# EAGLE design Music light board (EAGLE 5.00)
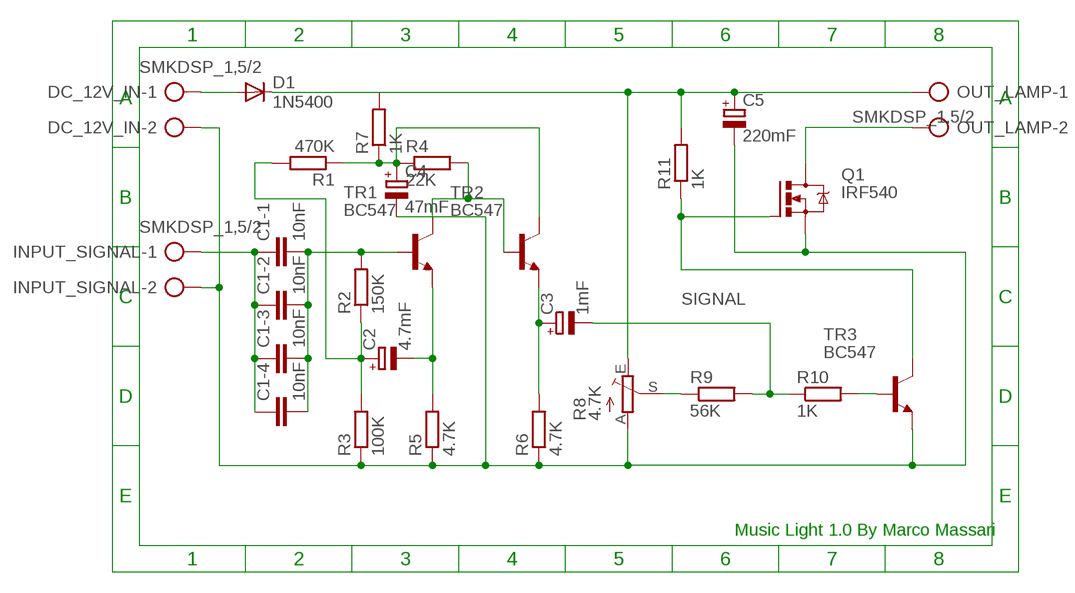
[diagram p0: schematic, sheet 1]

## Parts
C1-1  10nF  C-EU050-024X044  [C050-024X044]
C1-2  10nF  C-EU050-024X044  [C050-024X044]
C1-3  10nF  C-EU050-024X044  [C050-024X044]
C1-4  10nF  C-EU050-024X044  [C050-024X044]
C2  4.7mF  CPOL-EUE5-5  [E5-5]
C3  1mF  CPOL-EUE5-5  [E5-5]
C4  47mF  CPOL-EUE5-6  [E5-6]
C5  220mF  CPOL-EUE5-8.5  [E5-8,5]
D1  1N5400  [DO201-15]
DC_12V_IN  SMKDSP_1,5/2  [SMKDSP_1,5/2]
INPUT_SIGNAL  SMKDSP_1,5/2  [SMKDSP_1,5/2]
OUT_LAMP  SMKDSP_1,5/2  [SMKDSP_1,5/2]
Q1  IRF540  [TO220BV]
R1  470K  R-EU_0207/10  [0207/10]
R2  150K  R-EU_0207/10  [0207/10]
R3  100K  R-EU_0207/10  [0207/10]
R4  22K  R-EU_0207/10  [0207/10]
R5  4.7K  R-EU_0207/10  [0207/10]
R6  4.7K  R-EU_0207/10  [0207/10]
R7  1K  R-EU_0207/10  [0207/10]
R8  4.7K  TRIM_EU-LI10  [LI10]
R9  56K  R-EU_0207/10  [0207/10]
R10  1K  R-EU_0207/10  [0207/10]
R11  1K  R-EU_0207/10  [0207/10]
TR1  BC547  [TO92]
TR2  BC547  [TO92]
TR3  BC547  [TO92]

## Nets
N$1: D1.A DC_12V_IN.1
N$2: C1-1.1 C1-2.1 C1-3.1 C1-4.1 INPUT_SIGNAL.1
N$3: C1-1.2 C1-2.2 C1-3.2 C1-4.2 R2.2 TR1.2(B)
N$4: R8.S R9.1
N$5: R4.2 TR1.3(C) TR2.2(B)
N$6: C2.- R5.2 TR1.1(E)
N$7: C4.- C5.- DC_12V_IN.2 INPUT_SIGNAL.2 Q1.S R3.1 R5.1 R6.1 R8.A TR3.1(E)
N$8: C4.+ R1.1 R4.1 R7.1 TR2.3(C)
N$9: C5.+ D1.C OUT_LAMP.1 R7.2 R8.E R11.2
N$11: C3.+ R6.2 TR2.1(E)
N$13: Q1.G R11.1 TR3.3(C)
N$14: R10.2 TR3.2(B)
N$15: C2.+ R1.2 R2.1 R3.2
N$16: OUT_LAMP.2 Q1.D
SIGNAL: C3.- R9.2 R10.1

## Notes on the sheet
- Music Light 1.0 By Marco Massari

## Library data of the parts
C1-1-C1-4 = rcl:C-EU: CAPACITOR, European symbol
C2-C5 = rcl:CPOL-EU: POLARIZED CAPACITOR, European symbol
D1 = diode:1N5400: DIODE
DC_12V_IN INPUT_SIGNAL OUT_LAMP = con-phoenix-smkdsp:SMKDSP_1,5/2: Printklemme, Nennstrom: 17,5 A, Bemessungsspannung: 250 V, Raster: 5,0 mm
Q1 = transistor-power:IRF540: HEXFET Power MOSFET
R1-R7 = resistor:R-EU_: RESISTOR, European symbol
R8 = pot:TRIM_EU-: POTENTIOMETER
R9-R11 = rcl:R-EU_: RESISTOR, European symbol
TR1-TR3 = transistor-npn:BC547*: NPN Transistor

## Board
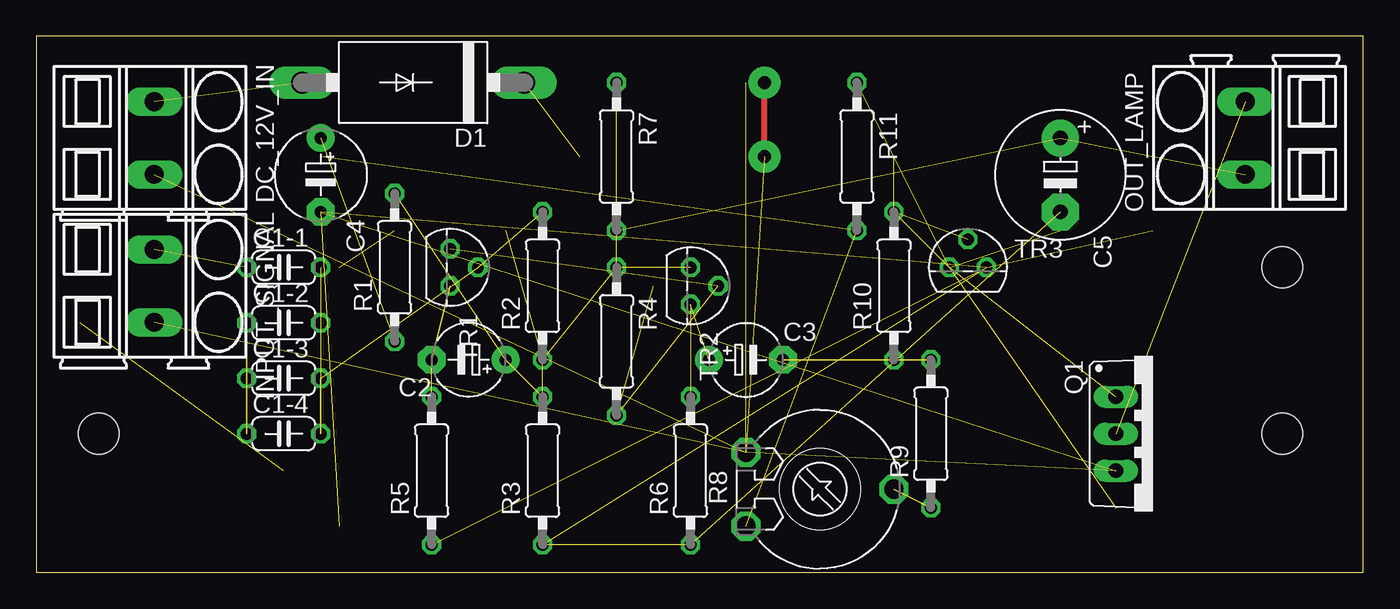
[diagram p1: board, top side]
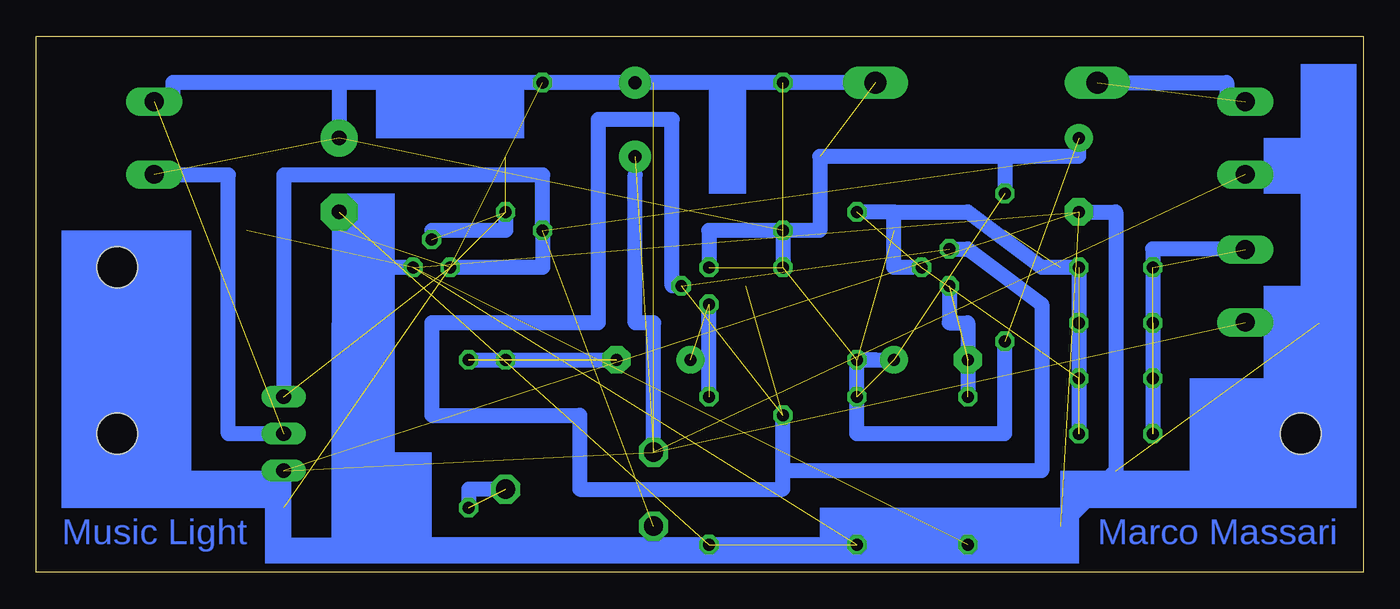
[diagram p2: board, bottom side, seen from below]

Size 91.11 x 36.82 mm. Coordinates in mm from the lower left corner, seen from the top.
Outline: 0,0 91.11,0 91.11,36.82 0,36.82 0,0
Copper layers (1*16): Top 0.035mm / dielectric 1.5mm / Bottom 0.035mm
Design rules "default": minimum track width 10mil, minimum drill 24mil, track to track 8mil, track to pad 8mil, pad to pad 8mil, via to via 8mil, smd to smd 8mil, copper to edge 40mil, drill to drill 8mil, minimum pad ring 10mil, minimum via ring 8mil, stop-mask expansion 4mil, vias tented up to drill 0mil, thermal gap 10mil
Holes 2.8 mm at 4.28,9.52 85.56,9.52 85.56,20.95

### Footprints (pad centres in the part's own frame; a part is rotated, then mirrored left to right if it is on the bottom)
C050-024X044 = drill 0.813 octagon: 1 -2.54,0; 2 2.54,0
E5-5 = drill 0.813 pad 1.905 round: + -2.54,0 | drill 0.813 pad 1.905 octagon: - 2.54,0
E5-6 = drill 0.813 pad 1.905 round: + -2.54,0 | drill 0.813 pad 1.905 octagon: - 2.54,0
E5-8,5 = drill 1.016 pad 2.54 round: + -2.54,0 | drill 1.016 pad 2.54 octagon: - 2.54,0
DO201-15 = drill 1.499 long: A 7.62,0; C -7.62,0
SMKDSP_1,5/2 = drill 1.3 pad 1.676 long: 1 -2.5,0; 2 2.5,0
TO220BV = drill 1.016 long: D 0,-2.54; G -2.54,-2.54; S 2.54,-2.54
0207/10 = drill 0.813 octagon: 1 -5.08,0; 2 5.08,0
LI10 = drill 1.321 octagon: A -2.54,-5.08; E 2.54,-5.08; S 0,5.08
TO92 = drill 0.813 octagon: 1 1.27,0; 2 0,1.905; 3 -1.27,0

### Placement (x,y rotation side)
C1-1  16.98,20.95 0 top
C1-2  16.98,17.14 0 top
C1-3  16.98,13.33 0 top
C1-4  16.98,9.52 0 top
C2  29.68,14.6 180 top
C3  48.73,14.6 0 top
C4  19.52,27.3 270 top
C5  70.32,27.3 270 top
D1  25.87,33.65 180 top
DC_12V_IN  8.09,29.84 270 top
INPUT_SIGNAL  8.09,19.68 270 top
OUT_LAMP  83.02,29.84 90 top
Q1  76.67,9.52 270 top
R1  24.6,20.95 90 top
R2  34.76,19.68 90 top
R3  34.76,6.98 90 top
R4  39.84,15.87 270 top
R5  27.14,6.98 90 top
R6  44.92,6.98 90 top
R7  39.84,28.57 270 top
R8  53.81,5.71 270 top
R9  61.43,9.52 90 top
R10  58.89,19.68 90 top
R11  56.35,28.57 270 top
TR1  28.41,20.95 270 top
TR2  44.92,19.68 270 top
TR3  63.97,20.95 0 top

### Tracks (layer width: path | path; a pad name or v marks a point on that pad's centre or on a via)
N$1  (1 unrouted)
N$2  (4 unrouted)
  Bottom 1.016: C1-2.1 C1-1.1 14.44,22.22 8.09,22.22 | C1-2.1 C1-4.1 C1-2.1
N$3  (6 unrouted)
  Bottom 1.016: C1-4.2 C1-1.2 20.79,20.95 22.06,20.95 27.14,24.76
N$4  (3 unrouted)
  Bottom 1.016: R8.S 61.43,5.71 R9.1
N$5  (3 unrouted)
  Bottom 1.016: 47.46,19.68 47.46,31.11 52.54,31.11 52.54,17.14 63.97,17.14 63.97,10.79 53.81,10.79 53.81,5.71 39.84,5.71 39.84,6.98 | TR1.3 27.14,22.22 22.06,18.41 22.06,6.98 39.84,6.98 | 39.84,6.98 R4.2
N$6  (3 unrouted)
  Bottom 1.016: TR1.1 28.41,17.14 27.14,17.14 C2.- R5.2
N$7  (via drill 0.9 pad 2.18)  (14 unrouted)
  Top 0.406: v50,28.57 50,33.65
  Bottom 1.016: 6.82,27.3 3.01,27.3 3.01,17.14 6.82,17.14 | C4.- 16.98,24.76 16.98,6.98 20.79,3.17 R3.1 R6.1 48.73,1.9 | 48.73,1.9 48.73,3.17 | R8.A 48.73,17.14 50,17.14 50,27.3 | 48.73,1.9 70.32,1.9 | 70.32,1.9 70.32,17.14 | TR3.1 70.32,20.95 | Q1.S 74.13,1.9 70.32,1.9
N$8  (via drill 0.9 pad 2.18)  (4 unrouted)
  Bottom 1.016: R1.1 24.6,9.52 34.76,9.52 34.76,14.6 | 34.76,33.65 R7.1 v50,33.65 70.32,33.65 | 70.32,33.65 70.32,29.84 | 70.32,33.65 81.75,33.65 81.75,32.38
N$9  (5 unrouted)
  Bottom 1.016: 19.52,29.84 19.52,28.57 24.6,28.57 | 24.6,28.57 24.6,26.03 | 24.6,28.57 37.3,28.57 37.3,23.49 R7.2 | R7.2 39.84,20.95 | R7.2 44.92,23.49 44.92,20.95 | 62.7,20.95 56.35,20.95 R11.2 56.35,27.3 74.13,27.3 74.13,12.06
N$10
  Bottom 1.016: 16.98,33.65 9.36,33.65 9.36,32.38
N$11  (2 unrouted)
  Bottom 1.016: R6.2 44.92,14.6 | 44.92,14.6 TR2.1 | 44.92,14.6 C3.+
N$12
  Bottom 1.016: 75.4,9.52 77.94,9.52 77.94,27.3 81.75,27.3
N$13  (4 unrouted)
  Bottom 1.016: 70.32,23.49 70.32,17.14
N$14  (5 unrouted)
  Bottom 1.016: R10.2 58.89,23.49 63.97,23.49
N$15  (4 unrouted)
  Bottom 1.016: 30.95,20.95 32.22,20.95 32.22,23.49 32.22,24.76 | 33.49,14.6 R2.1 C2.+ | 32.22,24.76 34.76,24.76 | 32.22,24.76 27.14,24.76
N$16  (1 unrouted)
SIGNAL  (4 unrouted)
  Bottom 1.016: R9.2 C3.-
(copper drawn outside any net)
  shapes: Bottom area x22

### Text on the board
Bottom: Marco Massari | Music Light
